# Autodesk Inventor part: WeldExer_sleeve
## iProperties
Shininess: 64.0
Length Units: 11269
Angle Units: 11279
Time Units: 11290
Mass Units: 11286
Length Display Precision: 3
Angle Display Precision: 2
Compacted: True
Part Number: WeldExer_sleeve
Document SubType Name: Modeling
Created: 2003-07
Designer: Ronald Myers
Manufacturer: Standard
Standards Organization: Custom
Stock Number: WeldExer_sleeve
Density: 1 g/cm^3
Density: 0.0
Volumn: 0.0
Area: 0.0
PropertySet Name: Model Information
Control State: 0
Master: False
Checked Out: False
Author: Ronald Myers
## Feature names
1. Extrusion1
